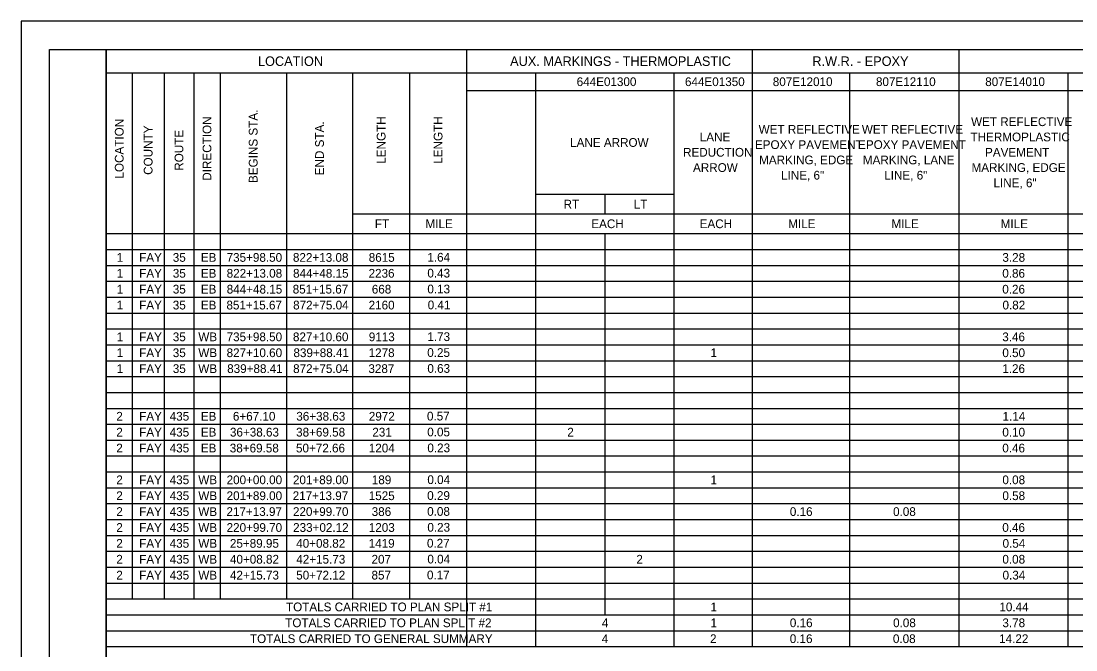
# Model space of a CAD drawing. Extents: x 0 to 34, y 0 to 22.
# Drawn here: x 0 to 18.61, y 10.92 to 22 of the extents above; entities that cross this region are included whole.
import ezdxf

# ---------------------------------------------------------------- set-up
doc = ezdxf.new("R2010")
doc.units = 0
for name, color, linetype in [('Default', 7, 'Continuous'), ('SH_Border', 7, 'Continuous'), ('SH_Cut_Line', 7, 'Continuous')]:
    doc.layers.add(name, color=color, linetype=linetype)

msp = doc.modelspace()

# ---------------------------------------------------------------- linework, layer by layer
at = {"layer": 'Default'}
for p, q in [((1.5, 21.5), (32.02, 21.5)), ((1.5, 21.5), (1.5, 17.975)), ((7.858, 21.5), (7.858, 10.975)), ((12.898, 21.5), (12.898, 10.975)), ((16.538, 21.5), (16.538, 10.975)), ((1.5, 21.088), (32.02, 21.088)), ((1.961, 21.088), (1.961, 11.815)), ((2.521, 21.088), (2.521, 11.815)), ((3.048, 21.088), (3.048, 11.815)), ((3.509, 21.088), (3.509, 11.815)), ((4.679, 21.088), (4.679, 11.815)), ((5.848, 21.088), (5.848, 11.815)), ((6.853, 21.088), (6.853, 11.815)), ((9.076, 21.088), (9.076, 10.975)), ((11.514, 21.088), (11.514, 10.975)), ((14.611, 21.088), (14.611, 10.975)), ((18.465, 21.088), (18.465, 10.975)), ((7.858, 20.775), (32.02, 20.775)), ((9.076, 18.947), (11.514, 18.947)), ((10.295, 18.947), (10.295, 18.601)), ((5.848, 18.601), (32.02, 18.601)), ((1.5, 18.255), (32.02, 18.255)), ((10.295, 18.255), (10.295, 11.535)), ((1.5, 17.975), (32.02, 17.975)), ((1.5, 17.695), (32.02, 17.695)), ((1.5, 17.415), (32.02, 17.415)), ((1.5, 17.135), (32.02, 17.135)), ((1.5, 16.855), (32.02, 16.855)), ((1.5, 16.575), (32.02, 16.575)), ((1.5, 16.295), (32.02, 16.295)), ((1.5, 16.015), (32.02, 16.015)), ((1.5, 15.735), (32.02, 15.735)), ((1.5, 15.455), (32.02, 15.455)), ((1.5, 15.175), (32.02, 15.175)), ((1.5, 14.895), (32.02, 14.895)), ((1.5, 14.615), (32.02, 14.615)), ((1.5, 14.335), (32.02, 14.335)), ((1.5, 14.055), (32.02, 14.055)), ((1.5, 13.775), (32.02, 13.775)), ((1.5, 13.495), (32.02, 13.495)), ((1.5, 13.215), (32.02, 13.215)), ((1.5, 12.935), (32.02, 12.935)), ((1.5, 12.655), (32.02, 12.655)), ((1.5, 12.375), (32.02, 12.375)), ((1.5, 12.095), (32.02, 12.095)), ((1.5, 12.095), (1.5, 10.975)), ((1.5, 11.815), (32.02, 11.815)), ((1.5, 11.535), (32.02, 11.535)), ((1.5, 11.255), (32.02, 11.255)), ((1.5, 10.975), (32.02, 10.975))]:
    msp.add_line(p, q, dxfattribs=at)
at = {"layer": 'SH_Border'}
for points in [[(0.5, 21.5), (1.5, 21.5), (1.5, 0.5), (0.5, 0.5)], [(1.5, 21.5), (33.5, 21.5), (33.5, 0.5), (1.5, 0.5)]]:
    msp.add_lwpolyline(points, close=True, dxfattribs=at)
at = {"layer": 'SH_Cut_Line'}
msp.add_lwpolyline([(0, 0), (34, 0), (34, 22), (0, 22)], close=True, dxfattribs=at)

# ---------------------------------------------------------------- texts
at = {"layer": 'Default'}
for s, height, p in [('LOCATION', 0.168, (4.178, 21.21)), ('AUX. MARKINGS - THERMOPLASTIC', 0.168, (8.626, 21.21)), ('R.W.R. - EPOXY', 0.168, (13.956, 21.21)), ('644E01300', 0.154, (9.8, 20.855)), ('644E01350', 0.154, (11.71, 20.855)), ('807E12010', 0.154, (13.259, 20.855)), ('807E12110', 0.154, (15.079, 20.855)), ('807E14010', 0.154, (17.006, 20.855)), ('WET REFLECTIVE ', 0.154, (16.757, 20.15)), ('WET REFLECTIVE ', 0.154, (13.01, 20.015)), ('WET REFLECTIVE ', 0.154, (14.83, 20.015)), ('LANE ARROW', 0.154, (9.684, 19.784)), ('LANE ', 0.154, (11.971, 19.881)), ('THERMOPLASTIC ', 0.154, (16.747, 19.881)), ('REDUCTION ', 0.154, (11.676, 19.611)), ('EPOXY PAVEMENT ', 0.154, (12.944, 19.746)), ('EPOXY PAVEMENT ', 0.154, (14.764, 19.746)), ('PAVEMENT ', 0.154, (17.003, 19.611)), ('MARKING, EDGE ', 0.154, (13.018, 19.476)), ('MARKING, LANE ', 0.154, (14.848, 19.476)), ('ARROW', 0.154, (11.852, 19.342)), ('LINE, 6"', 0.154, (13.405, 19.207)), ('LINE, 6"', 0.154, (15.225, 19.207)), ('MARKING, EDGE ', 0.154, (16.765, 19.342)), ('LINE, 6"', 0.154, (17.152, 19.072)), ('RT', 0.154, (9.569, 18.697)), ('LT', 0.154, (10.807, 18.697)), ('FT', 0.154, (6.24, 18.351)), ('MILE', 0.154, (7.133, 18.351)), ('EACH', 0.154, (10.058, 18.351)), ('EACH', 0.154, (11.969, 18.351)), ('MILE', 0.154, (13.532, 18.351)), ('MILE', 0.154, (15.352, 18.351)), ('MILE', 0.154, (17.279, 18.351)), ('1', 0.154, (1.685, 17.758)), ('FAY', 0.154, (2.083, 17.758)), ('35', 0.154, (2.676, 17.758)), ('EB', 0.154, (3.17, 17.758)), ('735+98.50', 0.154, (3.625, 17.758)), ('822+13.08', 0.154, (4.795, 17.758)), ('8615', 0.154, (6.132, 17.758)), ('1.64', 0.154, (7.166, 17.761)), ('3.28', 0.154, (17.309, 17.758)), ('1', 0.154, (1.685, 17.478)), ('FAY', 0.154, (2.083, 17.478)), ('35', 0.154, (2.676, 17.478)), ('EB', 0.154, (3.17, 17.478)), ('822+13.08', 0.154, (3.626, 17.478)), ('844+48.15', 0.154, (4.797, 17.478)), ('2236', 0.154, (6.129, 17.478)), ('0.43', 0.154, (7.166, 17.481)), ('0.86', 0.154, (17.307, 17.478)), ('1', 0.154, (1.685, 17.198)), ('FAY', 0.154, (2.083, 17.198)), ('35', 0.154, (2.676, 17.198)), ('EB', 0.154, (3.17, 17.198)), ('844+48.15', 0.154, (3.627, 17.198)), ('851+15.67', 0.154, (4.791, 17.198)), ('668', 0.154, (6.186, 17.198)), ('0.13', 0.154, (7.166, 17.201)), ('0.26', 0.154, (17.307, 17.198)), ('1', 0.154, (1.685, 16.918)), ('FAY', 0.154, (2.083, 16.918)), ('35', 0.154, (2.676, 16.918)), ('EB', 0.154, (3.17, 16.918)), ('851+15.67', 0.154, (3.622, 16.918)), ('872+75.04', 0.154, (4.798, 16.918)), ('2160', 0.154, (6.13, 16.918)), ('0.41', 0.154, (7.172, 16.921)), ('0.82', 0.154, (17.311, 16.918)), ('1', 0.154, (1.685, 16.358)), ('FAY', 0.154, (2.083, 16.358)), ('35', 0.154, (2.676, 16.358)), ('WB', 0.154, (3.126, 16.358)), ('735+98.50', 0.154, (3.625, 16.358)), ('827+10.60', 0.154, (4.795, 16.358)), ('9113', 0.154, (6.133, 16.358)), ('1.73', 0.154, (7.166, 16.361)), ('3.46', 0.154, (17.307, 16.358)), ('1', 0.154, (1.685, 16.078)), ('FAY', 0.154, (2.083, 16.078)), ('35', 0.154, (2.676, 16.078)), ('WB', 0.154, (3.126, 16.078)), ('827+10.60', 0.154, (3.625, 16.078)), ('839+88.41', 0.154, (4.804, 16.078)), ('1278', 0.154, (6.13, 16.078)), ('0.25', 0.154, (7.164, 16.081)), ('1', 0.154, (12.161, 16.078)), ('0.50', 0.154, (17.308, 16.078)), ('1', 0.154, (1.685, 15.798)), ('FAY', 0.154, (2.083, 15.798)), ('35', 0.154, (2.676, 15.798)), ('WB', 0.154, (3.126, 15.798)), ('839+88.41', 0.154, (3.635, 15.798)), ('872+75.04', 0.154, (4.798, 15.798)), ('3287', 0.154, (6.126, 15.798)), ('0.63', 0.154, (7.166, 15.801)), ('1.26', 0.154, (17.307, 15.798)), ('2', 0.154, (1.679, 14.958)), ('FAY', 0.154, (2.083, 14.958)), ('435', 0.154, (2.621, 14.958)), ('EB', 0.154, (3.17, 14.958)), ('6+67.10', 0.154, (3.736, 14.958)), ('36+38.63', 0.154, (4.854, 14.958)), ('2972', 0.154, (6.133, 14.958)), ('0.57', 0.154, (7.159, 14.961)), ('1.14', 0.154, (17.312, 14.958)), ('2', 0.154, (1.679, 14.678)), ('FAY', 0.154, (2.083, 14.678)), ('435', 0.154, (2.621, 14.678)), ('EB', 0.154, (3.17, 14.678)), ('36+38.63', 0.154, (3.684, 14.678)), ('38+69.58', 0.154, (4.851, 14.678)), ('231', 0.154, (6.195, 14.678)), ('0.05', 0.154, (7.164, 14.681)), ('2', 0.154, (9.634, 14.678)), ('0.10', 0.154, (17.308, 14.678)), ('2', 0.154, (1.679, 14.398)), ('FAY', 0.154, (2.083, 14.398)), ('435', 0.154, (2.621, 14.398)), ('EB', 0.154, (3.17, 14.398)), ('38+69.58', 0.154, (3.681, 14.398)), ('50+72.66', 0.154, (4.849, 14.398)), ('1204', 0.154, (6.133, 14.398)), ('0.23', 0.154, (7.166, 14.401)), ('0.46', 0.154, (17.307, 14.398)), ('2', 0.154, (1.679, 13.838)), ('FAY', 0.154, (2.083, 13.838)), ('435', 0.154, (2.621, 13.838)), ('WB', 0.154, (3.126, 13.838)), ('200+00.00', 0.154, (3.625, 13.838)), ('201+89.00', 0.154, (4.795, 13.838)), ('189', 0.154, (6.186, 13.838)), ('0.04', 0.154, (7.166, 13.841)), ('1', 0.154, (12.161, 13.838)), ('0.08', 0.154, (17.309, 13.838)), ('2', 0.154, (1.679, 13.558)), ('FAY', 0.154, (2.083, 13.558)), ('435', 0.154, (2.621, 13.558)), ('WB', 0.154, (3.126, 13.558)), ('201+89.00', 0.154, (3.625, 13.558)), ('217+13.97', 0.154, (4.791, 13.558)), ('1525', 0.154, (6.132, 13.558)), ('0.29', 0.154, (7.163, 13.561)), ('0.58', 0.154, (17.309, 13.558)), ('2', 0.154, (1.679, 13.278)), ('FAY', 0.154, (2.083, 13.278)), ('435', 0.154, (2.621, 13.278)), ('WB', 0.154, (3.126, 13.278)), ('217+13.97', 0.154, (3.622, 13.278)), ('220+99.70', 0.154, (4.795, 13.278)), ('386', 0.154, (6.184, 13.278)), ('0.08', 0.154, (7.163, 13.281)), ('0.16', 0.154, (13.56, 13.278)), ('0.08', 0.154, (15.381, 13.278)), ('2', 0.154, (1.679, 12.998)), ('FAY', 0.154, (2.083, 12.998)), ('435', 0.154, (2.621, 12.998)), ('WB', 0.154, (3.126, 12.998)), ('220+99.70', 0.154, (3.625, 12.998)), ('233+02.12', 0.154, (4.798, 12.998)), ('1203', 0.154, (6.133, 12.998)), ('0.23', 0.154, (7.166, 13.001)), ('0.46', 0.154, (17.307, 12.998)), ('2', 0.154, (1.679, 12.718)), ('FAY', 0.154, (2.083, 12.718)), ('435', 0.154, (2.621, 12.718)), ('WB', 0.154, (3.126, 12.718)), ('25+89.95', 0.154, (3.683, 12.718)), ('40+08.82', 0.154, (4.853, 12.718)), ('1419', 0.154, (6.131, 12.718)), ('0.27', 0.154, (7.159, 12.721)), ('0.54', 0.154, (17.312, 12.718)), ('2', 0.154, (1.679, 12.438)), ('FAY', 0.154, (2.083, 12.438)), ('435', 0.154, (2.621, 12.438)), ('WB', 0.154, (3.126, 12.438)), ('40+08.82', 0.154, (3.684, 12.438)), ('42+15.73', 0.154, (4.854, 12.438)), ('207', 0.154, (6.181, 12.438)), ('0.04', 0.154, (7.166, 12.441)), ('2', 0.154, (10.853, 12.438)), ('0.08', 0.154, (17.309, 12.438)), ('2', 0.154, (1.679, 12.158)), ('FAY', 0.154, (2.083, 12.158)), ('435', 0.154, (2.621, 12.158)), ('WB', 0.154, (3.126, 12.158)), ('42+15.73', 0.154, (3.684, 12.158)), ('50+72.12', 0.154, (4.853, 12.158)), ('857', 0.154, (6.181, 12.158)), ('0.17', 0.154, (7.159, 12.161)), ('0.34', 0.154, (17.312, 12.158)), ('TOTALS CARRIED TO PLAN SPLIT #1', 0.154, (4.673, 11.598)), ('1', 0.154, (12.161, 11.598)), ('10.44', 0.154, (17.256, 11.598)), ('TOTALS CARRIED TO PLAN SPLIT #2', 0.154, (4.659, 11.318)), ('4', 0.154, (10.244, 11.318)), ('1', 0.154, (12.161, 11.318)), ('0.16', 0.154, (13.56, 11.318)), ('0.08', 0.154, (15.381, 11.318)), ('3.78', 0.154, (17.309, 11.318)), ('TOTALS CARRIED TO GENERAL SUMMARY', 0.154, (4.037, 11.038)), ('4', 0.154, (10.242, 11.038)), ('2', 0.154, (12.152, 11.038)), ('0.16', 0.154, (13.559, 11.038)), ('0.08', 0.154, (15.378, 11.038)), ('14.22', 0.154, (17.252, 11.038))]:
    msp.add_text(s, height=height, dxfattribs=at).set_placement(p)
for s, p in [('DIRECTION', (3.356, 19.187)), ('BEGINS STA.', (4.171, 19.147)), ('LENGTH', (6.428, 19.486)), ('LENGTH', (7.432, 19.486)), ('LOCATION', (1.808, 19.225)), ('COUNTY', (2.318, 19.29)), ('END STA.', (5.341, 19.283)), ('ROUTE', (2.862, 19.363))]:
    msp.add_text(s, height=0.154, rotation=90, dxfattribs=at).set_placement(p)

doc.saveas('drawing.dxf')
